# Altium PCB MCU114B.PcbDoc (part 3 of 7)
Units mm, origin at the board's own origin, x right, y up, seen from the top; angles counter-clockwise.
Board outline 105.51 x 58.76 mm, 8 copper layers (Top Layer, GND 2, Signal Layer 3, Power 4, Power 5, Signal Layer 6, GND 7, Bottom), stack 1.554 mm thick; 444 components, 418 nets, 1811 pads, 981 vias.
Unrouted connection lines stored in the file: 3.
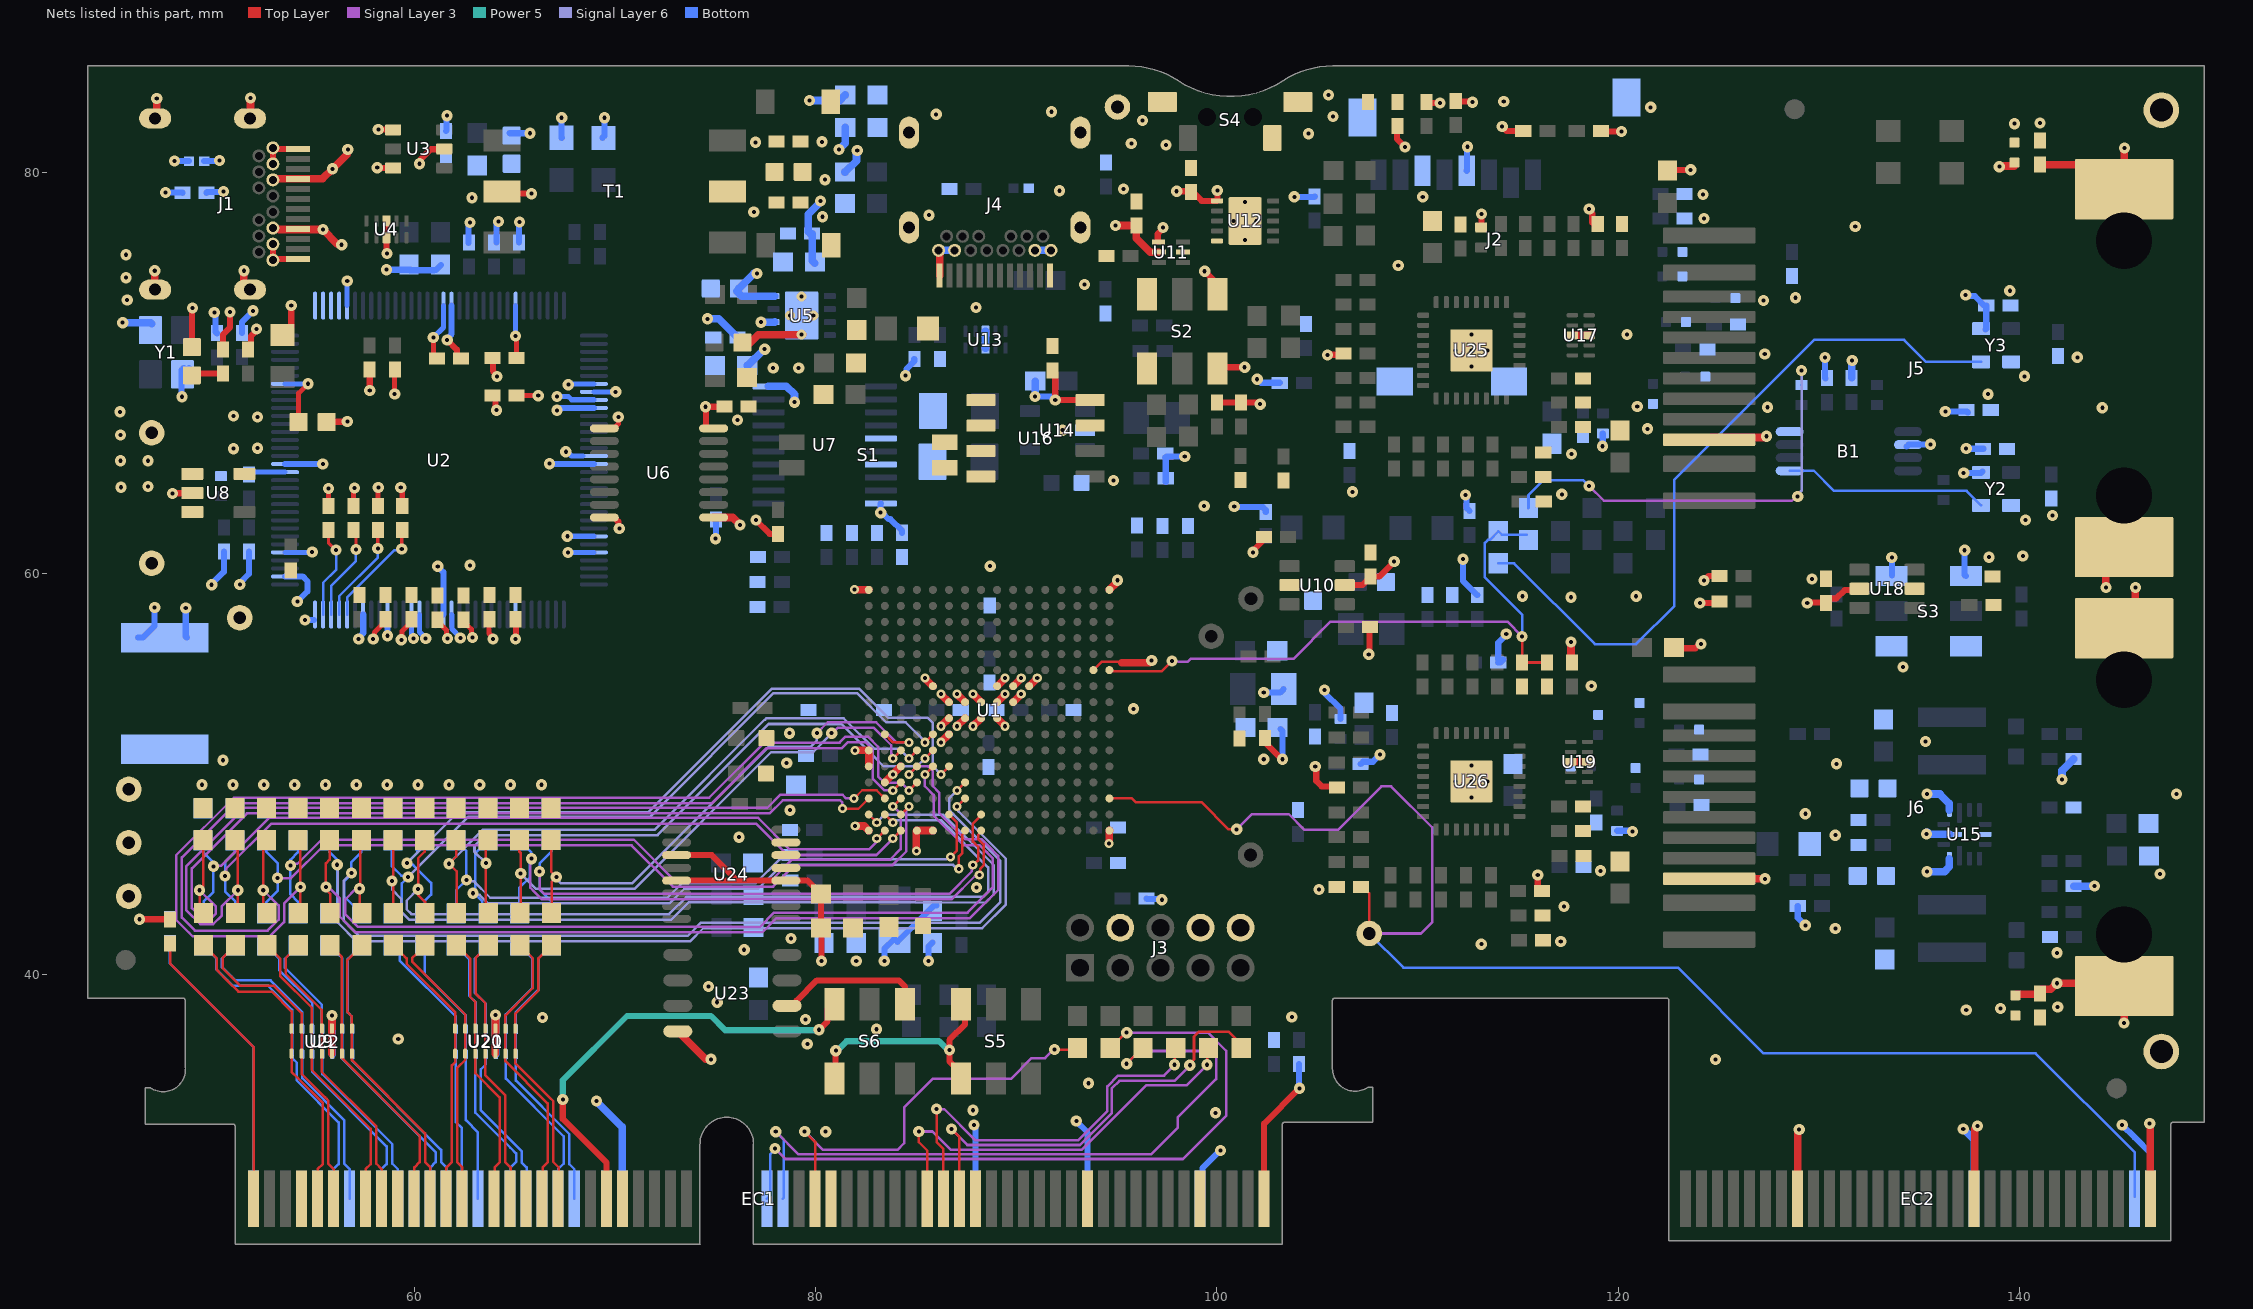
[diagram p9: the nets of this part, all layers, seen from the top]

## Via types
v1: diameter 0.559, hole 0.203, Top Layer to Bottom, tented both sides, 810 vias
v2: diameter 0.457, hole 0.203, Top Layer to Bottom, tented both sides, 153 vias
v3: diameter 0.5, hole 0.2, Top Layer to Bottom, tented both sides, 10 vias
v4: diameter 0.5, hole 0.2, Top Layer to Bottom, tented bottom, 4 vias
v5: diameter 0.5, hole 0.2, Top Layer to Bottom, tented top, 4 vias

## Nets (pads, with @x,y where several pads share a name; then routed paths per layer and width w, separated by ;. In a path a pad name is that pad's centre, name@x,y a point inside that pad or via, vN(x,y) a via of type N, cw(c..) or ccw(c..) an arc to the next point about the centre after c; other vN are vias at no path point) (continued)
3V3: B1.6 C31.1 C35.1 C36.1 C37.1 C40.2 C43.1 C64.1 C66.1 C86.2 C103.1 C152.1 C153.1 EC1.119 J2.4 J3.10 L3.1 L4.1 R1.2 R2.2 R34.1 R35.1 R36.2 R37.2 R39.2 R40.2 R42.2 R46.1 R51.2 R54.2 R61.2 R71.1 R73.1 R88.2 R89.2 R90.2 R100.2 R105.2 R106.2 R107.2 R108.1 R111.2 R130.2 R131.1 R133.2 R134.2 R137.2 R138.1 R142.1 R145.2 R151.2 R166.1 R168.2 R202.2 R204.2 R205.1 S2.1 S2.4 S3.1 S3.4 TP5.1 U6.16 U7.20 U10.5 U11.1 U12.1 U16.8 U18.5 Y2.4 Y3.4 | length 88.3
  Top Layer w0.305: v1(46.279,42.774) 46.28,42.772 47.655,42.772 R204.2@47.655,42.77 ; v1(74.499,68.326) C31.1@75.423,68.326 ; v1@74.524,68.377 74.524,67.292 74.568,67.248 U6.16@74.907,67.248 ; v1(77.02,62.671) 77.705,61.986 R100.2@78.105,61.986 ; C86.2@91.796,70.144 91.938,70.001 v1(91.938,68.662) 93.379,68.662 U16.8@93.469,68.572 ; U11.1@97.049,76.568 97.049,76.94 97.307,77.198 v1(97.307,77.267) ; v1(97.993,79.07) 98.765,79.07 99.246,78.589 U12.1@100.008,78.589 100.021,78.602 v1(100.021,79.102) ; v1(99.39,75.082) 100.023,74.45 S2.1@100.023,73.935 ; R54.2@99.997,68.537 R51.2@101.19,68.537 102.075,68.537 v1(102.159,68.453) v1@102.192,68.486 ; S2.4@100.023,70.235 100.082,70.294 v1(101.384,70.294) ; v1(101.799,61.068) 101.799,61.145 R39.2@102.343,61.689 ; EC1.119@102.357,28.836 102.357,32.583 v1(104.115,34.341) ; R46.1@102.387,51.8 102.387,51.587 v1@103.175,50.8 ; v1(104.902,50.394) 104.951,50.345 104.951,49.666 105.222,49.395 105.975,49.395 R142.1@105.975,49.347 ; v1(105.507,70.898) 105.525,70.916 106.263,70.916 R108.1@106.281,70.898 ; U10.5@106.375,59.428 107.235,59.428 C37.1@107.666,59.859 108.093,59.859 v1(108.839,60.604) ; v1(107.569,55.982) 107.606,56.018 107.606,57.316 R40.2@107.643,57.353 ; C36.1@108.976,82.303 108.976,81.684 v1(109.385,81.275) ; R36.2@110.452,83.523 110.504,83.471 v1(111.121,83.471) ; R37.2@111.934,83.573 111.969,83.537 112.719,83.537 v1(112.745,83.511) ; R134.2@113.178,77.266 113.2,77.287 v1(113.2,77.934) ; v1(114.224,82.296) 114.452,82.067 R111.2@115.275,82.067 ; v1(115.999,44.975) 115.999,44.264 R151.2@116.126,44.137 ; v1(118.563,78.188) 118.563,78.119 118.715,77.967 118.715,77.518 R107.2@118.817,77.416 ; R89.2@119.142,82.067 119.167,82.042 v1(120.167,82.042) ; v1(124.079,58.547) 124.982,58.547 R138.1@125.051,58.615 ; v1(124.289,59.668) 124.501,59.88 R137.2@125.06,59.88 ; v1(129.435,58.539) 129.461,58.564 C103.1@130.35,58.564 ; C103.1@130.364,58.549 130.364,58.619 130.511,58.767 130.882,58.767 131.298,59.182 131.983,59.182 U18.5@132.077,59.276
  Bottom w0.305: v1(46.279,42.774) 46.286,42.781 47.787,42.781 R205.1@47.794,42.788 ; v1(75.006,61.747) 75.02,61.762 75.02,62.697 R1.2@75.034,62.711 ; U7.20@83.242,63.496 83.238,63.496 83.236,63.494 v1(83.236,63.043) 83.305,63.043 83.626,62.721 83.724,62.721 84.303,62.143 C35.1@84.303,62.043 ; v1(83.418,40.684) 83.418,41.3 83.9,41.783 L4.1@83.922,41.783 ; L4.1@84.07,41.637 85.886,43.453 C66.1@86.018,43.453 ; v1(84.48,69.875) 84.529,69.924 84.529,70.215 84.912,70.598 R71.1@84.912,70.698 ; v1(90.932,68.834) 91.766,68.834 v1(91.938,68.662) ; R202.2@96.482,43.807 96.512,43.776 97.222,43.776 v1(97.252,43.746) ; R105.2@97.45,64.567 97.45,65.761 97.425,65.786 97.481,65.842 v1(98.397,65.842) ; v1(100.865,63.348) 100.893,63.319 102.287,63.319 102.435,63.172 R34.1@102.435,63.076 ; v1(102.006,69.698) 102.025,69.698 102.203,69.52 R88.2@103.134,69.52 ; v1(102.337,54.077) 103.154,54.077 L3.1@103.324,54.246 ; C64.1@103.162,52.262 103.273,52.15 v1(103.273,50.749) ; v1(103.861,78.791) 104.861,78.791 R61.2@104.877,78.807 ; R42.2@104.089,35.544 104.102,35.531 104.102,34.354 v1(104.115,34.341) ; v1(105.359,54.204) 105.359,54.077 106.172,53.264 R168.2@106.172,52.757 ; R130.2@107.162,50.504 107.285,50.626 107.776,50.626 v1(108.128,50.978) ; v1(112.269,60.724) 112.269,59.647 R145.2@112.98,58.936 ; v1(112.395,63.932) 112.395,63.863 112.447,63.811 112.447,63.274 R35.1@112.595,63.127 ; J2.4@112.457,80.093 112.475,80.111 112.475,81.269 v1(112.492,81.287) ; R133.2@114.028,55.572 114.128,55.572 114.276,55.72 114.028,55.72 114.028,56.555 114.427,56.954 v1(114.427,56.989) ; v1(119.228,66.355) 119.238,66.365 119.238,66.984 R131.1@119.249,66.995 ; R166.1@119.96,47.183 120.689,47.183 v1(120.722,47.149) ; R2.2@128.96,43.426 128.96,42.846 v1(129.337,42.469) ; v1(130.324,70.782) 130.324,69.766 R73.1@130.35,69.74 ; S3.4@133.651,59.91 v1(133.651,60.814) ; B1.6@134.388,66.337 134.495,66.443 135.571,66.443 v1(135.581,66.453) ; v1(136.319,68.089) 137.385,68.089 C43.1@137.436,68.039 ; v1(137.233,65.016) 138.097,65.016 Y2.4@138.173,65.092 ; v1(137.283,61.17) 137.283,59.945 S3.1@137.345,59.883 ; v1(137.334,73.895) 137.382,73.847 137.784,73.847 138.259,73.373 C153.1@138.359,73.373 ; v1(137.359,66.25) 137.379,66.23 138.218,66.23 C152.1@138.224,66.235 ; Y3.4@138.325,72.179 138.359,72.212 C153.1@138.359,73.347
  Bottom w0.381: v1(90.932,68.834) 90.937,68.839 90.937,69.597 R90.2@90.942,69.602
5V0: C51.1 C53.2 C54.2 R20.1 R21.2 R28.1 R29.1 R53.2 R93.2 R99.2 R103.2 TP9.1 U11.2 U15.7 U15.11 | length 7.4
  Top Layer w0.381: v1@94.945,77.353 v1(94.945,77.368) 94.952,77.362 C51.1@95.982,77.362 95.982,76.732 96.684,76.029 U11.2@97.108,76.029
  Bottom w0.381: v1(135.403,45.143) 136.278,45.143 136.523,45.387 U15.7@136.523,45.795 ; v1(135.403,49.014) 136.05,49.014 136.523,48.542 U15.11@136.523,48.22 ; R103.2@142.713,44.425 v1(143.754,44.425)
  other v1: 147.839,49.014 77.876,70.256 79.146,70.256 95.733,81.458
20MHZ_CLK: R70.1 Y3.3 | length 36.2
  Bottom w0.132: R70.1@114.027,60.521 114.815,60.521 118.847,56.49 120.904,56.49 122.805,58.39 122.805,64.69 129.775,71.66 134.26,71.66 135.354,70.566 Y3.3@138.102,70.566
25MHZ_CLK: B1.1 Y2.3 | length 10.3
  Bottom w0.127: B1.1@128.557,65.133 129.764,65.133 130.768,64.129 137.376,64.129 Y2.3@138.102,63.404
ADC_3V0_REF: S6.6 U23.6 | length 7.4
  Top Layer w0.305: U23.6@78.569,38.456 78.915,38.456 79.051,38.592 79.051,38.716 80.057,39.722 84.138,39.722 84.439,39.42 S6.6@84.439,38.617
ADC_REF: C123.1 R57.2 U24.3 U24.5 U24.12 | length 14.2
  Top Layer w0.305: U24.5@73.064,44.698 76.094,44.698 ; U24.3@73.064,45.968 74.824,45.968 76.094,44.698 ; C123.1@80.251,42.378 80.289,42.34 v1(80.289,40.684) ; C123.1@80.264,42.378 R57.2@80.264,43.764 ; R57.2@80.317,43.973 79.592,44.698 U24.12@78.514,44.698 76.094,44.698
DEBUG_ID4: R3.1 U2.63 | length 4.7
  Top Layer w0.159: R3.1@55.698,62.18 55.698,61.541 56.059,61.181 v1(56.08,61.181)
  Bottom w0.127: U2.63@55.435,57.966 55.435,59.55 56.08,60.195 v1(56.08,61.181)
DEBUG_ID5: R4.1 U2.62 | length 4.8
  Top Layer w0.159: R4.1@56.944,62.181 57.071,62.054 v1(57.071,61.206)
  Bottom w0.127: U2.62@55.835,57.966 55.835,59.391 57.071,60.627 v1(57.071,61.206)
DEBUG_ID6: R5.1 U2.61 | length 5
  Top Layer w0.159: v1(58.163,61.257) R5.1@58.163,62.181
  Bottom w0.127: U2.61@56.235,57.966 56.235,58.877 58.163,60.804 v1(58.163,61.257)
DEBUG_ID7: R6.1 U2.60 | length 5.5
  Top Layer w0.159: v1(59.357,61.231) 59.357,62.155 R6.1@59.382,62.181
  Bottom w0.127: U2.60@56.635,57.966 56.635,58.82 58.997,61.181 59.306,61.181 v1(59.357,61.231)
EMU_0: EC1.2 R205.2 | length 14.4
  Bottom w0.127: R205.2@47.794,41.588 47.794,40.573 51.984,36.382 EC1.2@51.984,28.923
EMU_1: EC1.1 R204.1 | length 14.4
  Top Layer w0.127: R204.1@47.803,41.57 47.803,40.564 51.984,36.382 51.984,32.57 EC1.1@51.984,28.923
EMU_3V3: C2.1 C3.1 C4.1 C5.1 C6.1 C7.1 C8.1 C9.1 C18.2 C30.1 R3.2 R4.2 R5.2 R6.2 R7.1 R10.2 R13.2 R14.1 TP2.1 U2.7 U2.8 U2.9 U2.16 U2.26 U2.28 U2.39 U2.47 U2.51 U2.52 U2.69 U2.79 U2.90 U2.101 U2.113 U2.122 U6.1 U8.5 | length 41.5
  Top Layer w0.127: U6.1@69.431,67.273 U6.1@69.457,67.248
  Top Layer w0.254: C18.2@54.215,67.564 54.215,68.997 v1(54.689,69.471) ; R3.2@55.698,63.38 v1(55.699,64.254) ; R4.2@56.944,63.381 56.944,64.229 v1(56.994,64.279) ; v1(57.933,56.75) 57.991,56.809 57.991,57.072 58.549,57.63 C7.1@58.549,57.73 ; R5.2@58.163,63.381 58.163,64.279 v1(58.188,64.305) ; v1(59.004,68.961) 59.004,70.156 R7.1@59.03,70.182 ; v1(59.306,64.305) 59.382,64.229 R6.2@59.382,63.381 ; v1(59.334,56.703) 59.363,56.733 59.363,57.133 59.666,57.436 59.677,57.436 59.87,57.63 C6.1@59.87,57.73 ; v1(60.931,71.772) 60.931,70.918 C9.1@61.119,70.731 ; C5.1@61.166,57.704 61.166,57.604 61.583,57.187 61.583,56.834 v1(61.642,56.776) ; C4.1@62.461,57.704 62.461,57.604 62.828,57.237 62.828,56.885 v1(62.886,56.827) ; C3.1@63.706,57.73 63.706,57.016 63.985,56.736 v1@63.985,56.72 ; v1(65.021,71.849) 65.087,71.782 C8.1@65.087,70.756 C8.1@65.106,70.776 ; C30.1@65.046,68.877 v1(66.164,68.877) ; U6.1@69.431,67.273 69.968,67.273 70.155,67.46 v1(70.155,67.818)
  Top Layer w0.305: R14.1@51.686,71.179 51.833,71.326 51.833,71.851 52.118,72.135 v1(52.118,72.204) ; C2.1@65.026,57.73 65.052,57.704 v1@65.052,56.755
  Bottom w0.254: R10.2@51.737,64.956 51.847,65.066 U2.79@53.535,65.066 ; U2.69@53.535,61.066 54.869,61.066 v1(54.892,61.089) ; U2.90@53.535,69.466 53.538,69.468 54.686,69.468 v1(54.689,69.471) ; U2.101@56.635,73.366 56.635,74.589 v1(56.639,74.592) ; U2.52@59.835,57.966 59.835,56.88 v1(59.94,56.776) ; U2.51@60.235,57.966 60.235,57.09 v1(60.549,56.776) ; v1@60.906,71.747 v1(60.931,71.772) 61.435,72.277 U2.113@61.435,73.366 ; U2.47@61.835,57.966 61.862,57.939 61.862,57.238 62.277,56.824 v1(62.277,56.801) ; v1(65.021,71.849) 65.035,71.863 U2.122@65.035,73.366 ; v1@65.026,56.72 65.035,56.729 U2.39@65.035,57.966 ; v1(67.103,68.842) 67.658,68.842 67.828,68.672 68.935,68.672 U2.9@68.935,68.666 ; v1(67.535,66.083) 67.604,66.083 67.817,65.87 U2.16@68.388,65.87 ; v1(67.612,61.866) U2.26@68.935,61.866 ; v1(67.64,61.062) 67.642,61.064 68.934,61.064 U2.28@68.935,61.066 ; v1(67.661,69.425) 67.702,69.466 U2.7@68.935,69.466 ; U2.8@68.935,69.066 68.937,69.067 70.022,69.067 v1(70.024,69.069)
  other v1: 63.909,56.745 65.026,56.745 50.975,66.235 52.168,66.261 52.168,67.81 50.975,67.861
EMU_5V0: C16.1 C17.2 C20.1 C21.1 C22.1 J1.A4 J1.A9 J1.B4 J1.B9 R15.2 R18.2 T1.5 TP1.1 U3.2 U8.1 U8.3 | length 14.7
  Top Layer w0.305: TP1.1@46.885,67.023 TP1.1@46.96,67.097 ; C17.2@49.017,70.082 49.017,69.979 C16.1@50.441,69.979 ; v1(55.905,80.188) v1@55.931,80.213 ; v1@60.169,80.522 60.249,80.522 60.283,80.557 60.283,80.637 60.81,81.163 61.458,81.163 U3.2@61.475,81.18 ; T1.5@64.354,79.062 64.466,78.95 v1(65.833,78.95)
  Top Layer w0.381: J1.B4@52.932,77.235 52.998,77.169 53.242,77.169 53.246,77.165 v1(55.423,77.165) 56.151,76.437 56.329,76.437 v1(56.363,76.403) ; J1.B9@52.932,79.635 52.982,79.685 J1.A4@54.192,79.685 55.403,79.685 v1(55.905,80.188) ; v1@55.931,80.213 56.633,80.916 56.633,81.119 v1(56.667,81.153)
  Bottom w0.305: C20.1@49.507,80.57 49.522,80.586 50.247,80.586 v1(50.262,80.601) ; R15.2@49.624,78.996 49.652,79.024 50.438,79.024 v1(50.466,79.052)
  other v1: 45.364,64.313 46.707,64.347 45.336,65.634 46.707,65.634 45.336,66.921 45.314,68.072 45.665,73.641 45.614,74.759 45.614,75.902 62.861,78.747 60.235,80.439
EMU_GND: C1.2 C2.2 C3.2 C4.2 C5.2 C6.2 C7.2 C8.2 C9.2 C10.2 C11.2 C12.2 C13.2 C14.2 C15.2 C16.2 C17.1 C18.1 C19.2 C20.2 C21.2 C22.2 C30.2 C34.2 D1.1 D5.2 D6.2 J1.A1 J1.A12 J1.B1 J1.B12 J1.M1 J1.M2 J1.S1 J1.S2 J1.S3 J1.S4 R11.1 R12.1 R15.1 R16.1 R17.2 TP3.1 U2.10 U2.17 U2.48 U2.55 U2.58 U2.64 U2.66 U2.80 U2.114 U3.4 U3.6 U4.3@58.594,76.754 U4.8@58.594,77.589 U6.8 U8.2 Y1.2 Y1.4 | length 65
  Top Layer w0.305: v1(47.927,64) 47.939,64.013 48.904,64.013 U8.2@48.943,64.051 ; C17.1@48.89,71.394 48.89,73.118 v1@48.924,73.152 ; C16.2@50.441,71.179 50.441,71.925 50.8,72.284 v1(50.8,73.05) ; J1.M1@52.932,76.435 J1.B1@52.932,75.635 52.982,75.685 J1.A12@54.192,75.685 ; J1.M2@52.932,80.435 J1.B12@52.932,81.235 52.982,81.185 J1.A1@54.192,81.185 ; D1.1@53.413,71.908 53.45,71.908 53.848,72.306 v1(53.848,73.381) ; C18.1@55.615,67.564 55.628,67.577 56.629,67.577 v1(56.642,67.589) ; v1@57.756,69.142 v1(57.76,69.139) 57.76,70.179 C1.2@57.756,70.182 ; v1(58.136,80.245) 58.144,80.238 58.918,80.238 U3.6@58.925,80.23 ; v1(58.187,82.15) 58.197,82.14 58.915,82.14 U3.4@58.925,82.13 ; U4.8@58.594,77.589 U4.3@58.594,76.754 58.594,76.005 v1(58.626,75.973) ; v1(61.62,71.653) 62.107,71.167 62.107,70.879 62.255,70.731 C9.2@62.319,70.731 ; C30.2@63.887,68.928 64.031,68.784 64.031,68.204 v1(64.08,68.155) ; C8.2@63.887,70.756 63.903,70.741 63.903,70.102 64.105,69.9 v1(64.105,69.831) ; U6.8@69.457,62.803 69.956,62.803 70.157,62.602 70.157,62.304 v1(70.206,62.255)
  Top Layer w0.381: v1(47.041,75.108) 47.041,74.186 J1.S3@47.062,74.165 ; J1.S2@47.062,82.705 47.142,82.786 v1(47.142,83.693) ; v1(51.486,75.108) 51.486,74.471 J1.S4@51.792,74.165 ; J1.S1@51.792,82.705 51.816,82.729 v1(51.816,83.718)
  Bottom w0.305: C34.2@46.199,56.812 46.453,56.812 47.038,57.396 v1(47.038,58.31) ; v1(47.57,79.001) 47.572,78.998 48.422,78.998 R15.1@48.424,78.996 ; v1(48.027,80.576) 48.03,80.573 48.747,80.573 C20.2@48.75,80.57 ; v1@48.378,69.069 48.378,70.157 Y1.4@48.484,70.263 ; v1(48.587,58.285) 48.587,56.863 C34.2@48.638,56.812 ; Y1.4@48.617,70.131 Y1.4@48.752,70.266 ; v1(49.881,59.45) 49.881,59.489 50.491,60.098 C15.2@50.491,61.111 ; v1(50.013,73.025) 50.061,72.976 50.061,72.067 C14.2@50.136,71.991 ; v1(51.284,59.467) 51.284,59.536 51.741,59.993 R11.1@51.741,61.112 ; C13.2@51.384,71.999 51.384,72.547 v1(51.946,73.109) ; U2.66@53.535,59.866 54.412,59.866 54.657,59.621 54.657,59.122 v1(54.15,58.615) ; U2.80@53.535,65.466 55.412,65.466 v1(55.42,65.473) ; v1(54.53,57.69) U2.64@54.983,57.69 ; v1(57.209,56.745) 57.209,56.817 57.435,57.043 U2.58@57.435,57.966 ; v1(58.598,75.159) R16.1@59.794,75.159 ; U2.55@58.635,57.966 58.64,57.961 v1(58.64,56.907) ; R16.1@59.769,75.133 R17.2@60.973,75.133 ; R16.1@59.769,75.135 61.051,75.135 R17.2@61.318,75.402 ; v1(61.151,60.368) 61.435,60.084 U2.48@61.435,57.966 ; C22.2@61.56,82.072 61.588,82.1 61.588,82.808 v1(61.616,82.836) ; v1(61.62,71.653) 61.62,71.722 61.842,71.944 61.842,73.359 U2.114@61.835,73.366 ; C11.2@62.69,76.497 62.69,77.442 v1(62.76,77.513) ; C12.2@64.085,76.521 64.085,77.466 v1(64.181,77.562) ; C21.2@64.738,81.977 64.756,81.96 v1(65.748,81.96) ; C10.2@65.202,76.521 65.202,77.517 v1(65.222,77.537) ; v1(66.722,65.488) 66.733,65.477 68.924,65.477 U2.17@68.935,65.466 ; v1(67.09,68.148) 67.125,68.148 67.242,68.266 U2.10@68.935,68.266 ; D5.2@67.332,81.738 67.331,81.739 v1(67.331,82.735) ; D6.2@69.364,81.738 69.465,81.838 v1(69.465,82.735)
  Bottom w0.381: v1(45.441,72.517) 46.831,72.517 Y1.2@46.884,72.463
  other v1: 62.76,60.419 48.394,68.825 48.924,73.253
ERRORSTS: EC2.178 R38.2 TP11.1 U1.P16 | length 74.7
  Top Layer w0.127: U1.P16@94.641,48.795 95.763,48.795 95.944,48.614 98.521,48.614 98.526,48.61 99.225,48.61 100.577,47.257 v1(100.987,47.257) ; R38.2@107.161,44.508 107.161,44.495 107.512,44.144 107.52,44.144 107.594,44.07 TP11.1@107.594,42.062
  Signal Layer 3 w0.127: v1(100.987,47.257) 101.743,48.013 103.582,48.013 104.351,47.244 106.052,47.244 108.205,49.397 108.689,49.397 110.726,47.36 110.726,42.614 110.174,42.062 TP11.1@107.594,42.062
  Bottom w0.127: TP11.1@107.594,42.062 109.296,40.361 122.987,40.361 127.26,36.088 140.823,36.088 145.774,31.137 EC2.178@145.774,28.93
ETH1_EARTH: C101.2 C117.2 J5.10 J5.13 J5.14 J6.10 J6.13 J6.14 pad.6 R136.2 R170.2 | length 23.8
  Top Layer w0.381: J6.10@124.544,44.792 127.321,44.792 v1(127.326,44.787) ; J5.10@124.544,66.678 124.658,66.793 127.298,66.793 127.358,66.853 v1(127.406,66.853) ; v1(139.01,80.296) 139.044,80.33 139.75,80.33 C101.2@139.813,80.393 ; C117.2@139.813,38.981 139.863,39.031 140.982,39.031 R170.2@141.032,39.081 141.032,39.181 141.141,39.291 141.568,39.291 v1@141.858,39.58 ; R136.2@141.032,80.393 J5.13@144.01,80.393 ; v1(141.88,39.58) v1@141.858,39.58 ; v1(144.323,59.309) 144.323,60.417 J5.14@145.234,61.328 ; v1(145.233,37.599) 145.233,39.321 144.974,39.58 v1@141.858,39.58 ; J6.13@145.234,57.282 145.796,57.844 v1(145.796,59.309) ; J5.13@145.234,79.168 145.248,79.183 v1(145.248,81.221)
F28P65x_25MHZ_CLK: R65.2 R75.2 | length 22
  Signal Layer 3 w0.127: v1(118.563,64.37) 119.295,63.638 128.666,63.638 128.883,63.856 v1(128.956,63.856)
  Signal Layer 6 w0.127: v1(128.956,63.856) 128.956,63.947 129.155,64.146 v1(129.155,70.136)
  Bottom w0.132: R75.2@115.53,63.276 115.534,63.279 115.534,63.921 116.281,64.668 118.265,64.668 v1(118.563,64.37) ; R65.2@129.145,69.406 129.155,69.416 v1(129.155,70.136)
F28P65x_CLK: C126.2 R41.2 R70.2 R75.1 U1.F16 | length 32.4
  Top Layer w0.127: U1.F16@94.641,55.195 94.694,55.143 97.256,55.143 v1(97.765,55.651) ; v1(115.214,56.871) C126.2@115.214,55.566 115.221,55.572 R41.2@116.459,55.572
  Signal Layer 3 w0.127: v1(97.765,55.651) 97.796,55.62 98.554,55.62 98.691,55.757 103.816,55.757 105.666,57.607 114.478,57.607 v1(115.214,56.871)
  Bottom w0.127: v1(115.214,56.871) 115.214,57.963 113.361,59.816 113.361,61.536 113.51,61.685 113.615,61.685 114.027,62.096 R70.2@114.027,62.121 114.203,61.945 R75.1@115.459,61.945
GND: B1.4 C23.2 C24.1 C25.2 C26.1 C27.2 C28.1 C29.2 C31.2 C32.2 C33.2 C34.1 C35.2 C36.2 C37.2 C38.2 C39.2 C40.1 C41.1 C42.1 C43.2 C44.2 C45.1 C46.2 C47.2 C49.2 C51.2 C52.1 C53.1 C54.1 C55.2 C56.2 C57.2 C58.2 C59.2 C60.2 C61.2 C62.2 C63.1 C64.2 C65.2 C66.2 C67.2 C68.2 C69.2 C70.2 C71.2 C72.2 C73.2 C74.2 C75.2 C76.2 C77.2 C78.2 C79.2 C80.2 C81.2 C82.2 C83.2 C84.1 C85.1 C86.1 C87.1 C88.1 C89.2 C90.2 C91.2 C92.2 C93.2 C94.2 C95.1 C96.1 C97.2 C98.2 C99.2 C100.2 C101.1 C102.1 C103.2 C104.1 C105.2 C106.2 C107.2 C108.2 C109.2 C110.2 C111.1 C112.1 C113.2 C114.1 C115.2 C116.1 C117.1 C118.1 C119.1 C120.2 C121.2 C122.2 C123.2 C124.2 C125.2 C126.1 C128.2 C129.2 C130.2 C131.2 C132.2 C133.2 C134.2 C135.2 C136.2 C137.2 C138.2 C139.2 C140.2 C141.2 C142.2 C143.2 C144.2 C145.2 C146.2 C147.2 C148.2 C149.2 C150.2 C151.2 C152.2 C153.2 D2.1 D7.1 EC1.7 EC1.10 EC1.19 EC1.22 EC1.35 EC1.38 EC1.46 EC1.47 EC1.65 EC1.83 EC1.97 EC1.111 EC2.135 EC2.157 EC2.179 J2.6 J2.S1 J2.S2 J2.S3 J2.S4 J3.4 J3.8 J4.A1 J4.A12 J4.B1 J4.B12 J4.M1 J4.M2 J4.S1 J4.S2 J4.S3 J4.S4 R22.1 R23.1 R25.1 R26.1 R27.1 R31.1 R32.2 R38.1 R41.1 R43.1 R48.1 R69.2 R72.1 R74.2 R76.2 R77.1 R95.1 R104.1 R109.1 R112.1 R113.1 R123.1 R124.1 R125.1 R127.1 R128.1 R129.1 R132.1 R135.1 R136.1 R139.2 R140.2 R141.2 R143.1 R146.1 R147.1 R159.1 R160.1 R161.1 R162.1 R163.2 R167.1 R169.1 R170.1 R171.1 R206.1 S1.3 S1.4 S2.3 S2.6 S3.3 S3.6 S4.1 S4.2 S4.3 T1.2 TP8.1 U1.A1 U1.A16 U1.F15 U1.G5 U1.G9 U1.G10 U1.G11 U1.H6 U1.H7 U1.H8 U1.H9 U1.H10 U1.J6 U1.J7 U1.J8 U1.J9 U1.K6 U1.L1 U1.M1 U1.M3 U1.N2 U1.T1 U1.T4 U1.T5 U1.T16 U5.5 U5.9@79.299,72.868 U6.9 U7.10 U7.15 U7.17 U9.5 U9.10 U10.2 U11.5 U12.5 U12.11 U13.3@88.46,71.25 U13.8@88.46,72.085 U14.2 U15.2 U15.9 U16.1 U16.2 U16.3 U16.4 U16.7 U17.3@117.725,71.887 U17.8@118.56,71.887 U18.2 U19.3@117.641,50.618 U19.8@118.476,50.618 U20.5 U20.10 U21.5 U21.10 U22.5 U22.10 U23.4 U24.13 U24.14 U24.15 U25.33 U26.33 Y2.2 Y3.2 | length 59.1
  Top Layer w0.127: U1.F15@93.841,55.195 94.247,55.601 95.254,55.601 95.291,55.638
  Top Layer w0.305: R135.1@122.463,80.094 122.506,80.137 v1(123.622,80.137) ; R169.1@122.792,56.319 122.824,56.286 123.858,56.286 124.061,56.49 v1(124.13,56.49)
  Top Layer w0.381: U9.5@55.869,36.07 U9.10@55.869,37.32 ; U9.10@55.88,37.32 v1(55.88,37.973) ; U20.5@64.022,36.07 64.022,36.906 64.033,36.917 v1(64.033,37.998) ; U23.4@73.119,37.186 74.516,35.789 v1(74.778,35.789) ; U6.9@74.907,62.803 75.856,62.803 v1(76.225,62.433) ; C26.1@76.568,71.349 77.142,71.923 v5@79.35,71.923 ; v2(81.928,59.207) 81.936,59.199 82.638,59.199 U1.A1@82.641,59.195 ; v2(81.962,51.189) 81.968,51.195 U1.L1@82.641,51.195 U1.M1@82.641,50.395 ; v2(81.966,47.422) 82.414,47.422 U1.T1@82.641,47.195 ; U1.N2@83.441,49.595 v2(83.841,49.995) U1.M3@84.241,50.395 ; v2(85.014,46.177) 85.014,47.167 U1.T4@85.041,47.195 U1.T5@85.841,47.195 ; v2(85.441,54.795) U1.G5@85.841,54.395 ; J4.B1@86.125,76.126 86.175,76.076 J4.A12@86.175,74.866 ; v2@86.212,52.39 86.236,52.39 U1.J6@86.641,52.795 ; v2(86.241,51.595) U1.K6@86.641,51.995 ; v2(86.241,53.995) U1.H6@86.641,53.595 ; v2@87.012,52.39 87.036,52.39 U1.J7@87.441,52.795 ; v2(87.041,53.995) U1.H7@87.441,53.595 ; v2@87.812,52.39 87.836,52.39 U1.J8@88.241,52.795 ; v2(87.841,53.995) U1.H8@88.241,53.595 ; U1.J9@89.041,52.795 v2(89.441,52.395) ; U1.H9@89.041,53.595 v2(89.441,53.995) ; U1.G9@89.041,54.395 v2(89.441,54.795) ; U1.H10@89.841,53.595 v2(90.241,53.995) ; U1.G10@89.841,54.395 v2(90.241,54.795) ; U1.G11@90.641,54.395 v2(91.041,54.795) ; v2(94.626,46.557) 94.626,47.18 U1.T16@94.641,47.195 ; U1.A16@94.641,59.195 94.641,59.2 95.004,59.563 95.004,59.641 v1(95.038,59.675) ; 95.254,55.567 96.639,55.567 v1(96.749,55.677) ; U19.3@117.641,50.618 U19.8@118.476,50.618 ; v1(117.653,56.591) 117.653,55.619 R143.1@117.699,55.572 ; U17.3@117.725,71.887 U17.8@118.56,71.887 ; EC2.135@128.955,28.836 128.955,32.206 v1(129.032,32.283) ; EC2.157@137.755,28.836 137.783,28.865 137.783,32.323 v1(137.922,32.461) ; v1(146.507,32.588) 146.531,32.565 146.531,28.86 EC2.179@146.555,28.836
  Bottom w0.305: v1@85.623,40.64 85.623,41.415 C66.2@85.827,41.618
  Bottom w0.381: v1(55.88,37.973) 55.88,36.684 55.896,36.668 U22.10@55.896,36.043 ; v1(64.033,37.998) 64.033,36.684 64.049,36.668 U21.10@64.049,36.043 ; U7.10@77.642,69.346 78.533,69.346 78.941,68.938 v1(78.941,68.554) ; J4.B1@86.125,76.126 J4.M1@86.925,76.126 ; U13.3@88.46,71.25 U13.8@88.46,72.085 ; J4.M2@90.925,76.126 J4.B12@91.725,76.126 ; R74.2@131.648,69.764 131.648,70.612 v1(131.674,70.637) ; v1@135.382,47.117 135.43,47.117 135.54,47.007 U15.9@136.535,47.007 ; v1(142.138,49.733) 142.138,50.189 R206.1@142.708,50.759
  other v1: 80.493,32.182 99.924,33.122 87.833,33.249 93.599,34.595 124.866,35.785 79.578,36.551 59.182,36.805 83.033,37.287 79.484,37.781 66.37,37.871 103.734,37.897 137.363,38.249 139.065,38.329 141.921,38.397 75.082,38.633 74.651,39.421 82.017,40.684 85.623,40.684 141.884,41.097 76.429,41.25 113.182,41.529 117.145,41.656 78.765,41.808 130.835,42.316 117.308,43.401 105.091,44.253 88.011,44.348 147.026,45.026 119.126,45.187 76.175,46.863 130.835,46.965 135.373,47.027 129.337,48.031 78.715,48.209 49.403,49.479 50.941,49.479 52.479,49.479 54.017,49.479 55.554,49.479 57.092,49.479 58.63,49.479 60.168,49.479 61.706,49.479 63.244,49.479 64.782,49.479 66.319,49.479 130.886,50.521 78.548,50.563 50.444,50.698 102.337,50.749 135.331,51.638 78.689,52.051 95.834,53.264 118.669,54.407 134.214,55.347 117.653,58.826 115.24,58.877 120.904,58.877 129.678,59.733 88.697,60.376 138.492,60.825 140.183,60.884 140.321,62.679 141.667,62.908 99.365,63.373 117.196,63.957 106.756,64.084 94.844,64.643 117.678,65.964 92.3,67.158 121.474,67.226 76.094,67.658 144.145,68.275 127.457,68.301 120.957,68.342 138.441,68.953 140.27,69.842 142.9,70.79 127.316,70.96 120.447,71.933 87.986,73.279 127.256,73.629 128.854,73.762 139.533,74.109 93.396,74.422 109.042,75.362 131.826,77.318 124.293,77.716 80.34,77.8 85.649,77.876 76.911,78.029 110.261,78.791 124.242,78.91 92.151,79.096 95.337,79.189 97.46,81.382 76.987,81.509 104.572,81.94 139.762,82.44 141.032,82.466 96.291,82.601 105.791,82.804 86.004,82.906 91.753,83.035 121.626,83.253 114.3,83.541 105.562,83.871
  other v2: 86.241,52.395 87.041,52.395 87.841,52.395
  other v3: 112.685,48.849 111.885,49.649 112.685,49.649 113.485,49.649 112.685,50.449 112.685,70.337 111.885,71.137 112.685,71.137 113.485,71.137 112.685,71.937
  other v4: 101.408,76.639 100.833,77.589 101.983,77.589 101.408,78.539
  other v5: 79.299,71.918 78.724,72.868 79.874,72.868 79.299,73.818
HSEC_5V0: C27.1 C28.2 EC1.48 EC1.84 EC1.98 EC1.112 EC2.158 EC2.180 R22.2 R24.2 R28.2 TP4.1 U5.8 | length 32.6
  Bottom w0.305: v1(87.884,32.512) 87.957,32.439 EC1.84@87.957,28.95 ; v1@92.985,32.711 93.557,32.139 EC1.98@93.557,28.836 ; EC1.112@99.157,28.836 99.28,28.958 99.28,30.355 v1(100.173,31.249) ; v1(145.136,32.512) 145.754,31.894 146.555,31.093 EC2.180@146.555,28.95
  Bottom w0.381: v1(69.063,33.706) 70.357,32.411 EC1.48@70.357,28.836 ; v1(74.604,72.708) 75.161,72.708 C27.1@76.089,71.78 ; C28.2@76.062,74.092 76.311,73.843 U5.8@77.95,73.843 ; C28.2@76.163,74.219 76.911,74.966 v1(77.065,74.966) ; R22.2@76.582,70.382 76.607,70.382 77.422,71.197 v1(77.45,71.197) ; v1(81.153,81.153) 81.471,81.471 R28.2@81.471,82.245 ; R24.2@81.446,80.033 81.471,80.033 82.033,80.595 82.033,81.068 v1(82.067,81.102) ; v1@137.207,32.316 137.755,31.768 EC2.158@137.755,28.836
  other v1: 137.212,32.316 92.989,32.715
HSEC_ADC-VREFHI: EC1.45 S6.4 | length 22.9
  Top Layer w0.305: v1(67.386,33.782) 67.386,32.817 69.557,30.646 EC1.45@69.557,28.836 ; v1(80.162,37.262) 80.591,37.691 80.591,38.269 S6.4@80.939,38.617
  Power 5 w0.305: v1(67.386,33.782) 67.386,34.747 70.587,37.948 74.778,37.948 75.489,37.236 80.137,37.236 v1(80.162,37.262)
HSEC_ADC_A0A1_N: EC1.11 R173.2 U9.2 U9.13 | length 16.2
  Top Layer w0.124: R173.2@51.057,41.477 50.421,40.841 50.421,40.348 50.871,39.898 51.323,39.446 52.996,39.446 54.369,38.073 54.369,37.599 U9.13@54.369,37.32 U9.2@54.369,36.07 54.369,35.054 55.533,33.89 55.533,33.888 55.621,33.801 55.621,33.799 55.7,33.72 55.7,30.569 55.957,30.312 EC1.11@55.957,28.836
HSEC_ADC_A0A1_P: EC1.9 R172.2 U9.1 U9.14 | length 16.2
  Top Layer w0.124: R172.2@49.48,41.477 50.144,40.813 50.144,40.233 50.221,40.157 50.221,40.153 50.674,39.7 50.677,39.7 51.208,39.169 52.881,39.169 53.869,38.182 53.869,37.599 53.869,35.161 54.173,34.857 54.173,34.855 55.423,33.605 55.423,30.578 55.157,30.312 EC1.9@55.157,28.836
HSEC_ADC_A2A3_N: EC1.17 R175.2 U9.4 U9.11 | length 14.9
  Top Layer w0.124: R175.2@54.211,41.477 53.573,40.839 53.573,40.051 55.369,38.256 U9.11@55.369,37.32 55.369,36.349 U9.4@55.369,36.07 55.369,35.469 55.369,35.157 58.09,32.436 58.09,30.579 58.357,30.312 EC1.17@58.357,28.836
HSEC_ADC_A2A3_P: EC1.15 R174.2 U9.3 U9.12 | length 14.9
  Top Layer w0.124: R174.2@52.63,41.477 53.296,40.811 53.296,39.937 54.869,38.364 54.869,35.262 57.81,32.32 57.81,30.565 57.557,30.312 EC1.15@57.557,28.836
HSEC_ADC_A4A5_N: EC1.23 R177.2 U9.7 U9.8 | length 14.5
  Top Layer w0.124: R177.2@57.366,41.452 56.646,40.732 56.646,38.149 56.862,37.932 56.862,37.606 56.869,37.599 U9.8@56.869,37.32 56.869,36.349 U9.7@56.869,36.07 56.869,35.75 60.526,32.093 60.526,30.659 60.784,30.4 EC1.23@60.784,28.923
HSEC_ADC_A4A5_P: EC1.21 R176.2 U9.6 U9.9 | length 14.3
  Top Layer w0.124: R176.2@55.789,41.477 56.369,40.897 56.369,37.599 U9.6@56.369,36.07 ; U9.6@56.369,35.859 60.249,31.979 60.249,30.665 59.984,30.4 EC1.21@59.984,28.923
HSEC_ADC_A8A9_N: EC1.36 R179.2 U21.4 U21.11 | length 14.1
  Bottom w0.124: R179.2@63.649,41.461 63.649,41.436 63.236,41.023 63.211,41.023 62.992,40.804 62.992,39.116 63.549,38.559 U21.4@63.549,37.293 U21.11@63.549,36.043 63.549,35.915 63.549,35.542 63.299,35.292 63.299,33.245 65.337,31.208 65.337,30.646 65.584,30.399 EC1.36@65.584,28.923
HSEC_ADC_A8A9_P: EC1.34 R178.2 U21.3 U21.12 | length 13.9
  Bottom w0.124: R178.2@62.072,41.461 62.072,41.436 62.715,40.793 62.715,38.958 63.049,38.624 U21.12@63.049,36.043 63.022,36.016 63.022,33.131 64.775,31.378 65.06,31.093 65.06,30.674 64.784,30.399 EC1.34@64.784,28.923
HSEC_ADC_A10A11_N: EC1.42 R181.2 U21.7 U21.8 | length 14.6
  Bottom w0.124: R181.2@66.828,41.477 66.152,40.8 66.152,39.242 65.049,38.139 U21.7@65.049,37.293 U21.8@65.049,36.043 65.049,34.722 67.71,32.062 67.71,30.559 67.957,30.312 EC1.42@67.957,28.836
HSEC_ADC_A10A11_P: EC1.40 R180.2 U21.6 U21.9 | length 14.8
  Bottom w0.124: R180.2@65.226,41.461 65.875,40.813 65.875,39.357 64.549,38.031 U21.9@64.549,36.043 64.549,34.83 67.433,31.947 67.433,30.588 67.157,30.312 EC1.40@67.157,28.836
HSEC_ADC_A14B14C14A15B15C15_N: EC1.27 R183.2 U20.2 U20.13 | length 14.2
  Top Layer w0.124: R183.2@60.52,41.477 60.52,41.452 60.107,41.039 60.082,41.039 59.877,40.834 59.877,40.666 62.522,38.021 62.522,37.599 62.522,36.349 62.522,35.762 62.131,35.371 62.131,30.653 62.384,30.4 EC1.27@62.384,28.923
HSEC_ADC_A14B14C14A15B15C15_P: EC1.25 R182.2 U20.1 U20.14 | length 14
  Top Layer w0.124: R182.2@58.943,41.477 58.943,41.452 59.356,41.039 59.381,41.039 59.6,40.82 59.6,40.551 62.031,38.121 62.031,37.608 62.022,37.599 62.022,36.349 62.022,35.653 61.855,35.486 61.855,30.671 61.584,30.4 EC1.25@61.584,28.923
HSEC_ADC_B0B1_N: EC1.14 R185.2 U22.2 U22.13 | length 16.6
  Bottom w0.124: R185.2@51.057,41.477 51.057,41.452 50.658,41.053 50.633,41.053 50.393,40.813 50.393,40.39 51.06,39.723 52.817,39.723 54.396,38.144 U22.2@54.396,37.293 54.396,34.848 56.481,32.762 56.481,30.588 56.757,30.312 EC1.14@56.757,28.836
HSEC_ADC_B0B1_P: EC1.12 R184.2 U22.1 U22.14 | length 16.4
  Bottom w0.124: R184.2@49.48,41.477 49.48,41.452 50.116,40.816 50.116,40.275 50.945,39.446 52.702,39.446 53.896,38.252 U22.14@53.896,36.043 ; U22.14@53.869,35.876 53.913,35.876 53.934,35.855 53.934,35.811 54.119,35.626 54.119,34.733 56.205,32.647 56.205,30.56 55.957,30.312 EC1.12@55.957,28.836
HSEC_ADC_B2B3_N: EC1.20 R187.2 U22.4 U22.11 | length 15.2
  Bottom w0.124: R187.2@54.186,41.461 53.522,40.797 53.522,40.364 55.369,38.517 55.369,37.599 U22.4@55.369,37.293 ; U22.4@55.396,37.293 U22.11@55.396,36.043 55.396,35.048 58.881,31.562 58.881,30.588 59.157,30.312 EC1.20@59.157,28.836
HSEC_ADC_B2B3_P: EC1.18 R186.2 U22.3 U22.12 | length 15.2
  Bottom w0.124: R186.2@52.609,41.461 53.246,40.825 53.246,40.249 54.896,38.598 U22.12@54.896,36.043 54.896,35.156 58.605,31.447 58.605,30.56 58.357,30.312 EC1.18@58.357,28.836
HSEC_ADC_B4B5_N: EC1.26 R189.2 U22.7 U22.8 | length 14.9
  Bottom w0.124: U22.8@56.869,36.043 56.869,35.962 56.896,35.934 56.89,35.928 56.89,35.708 61.323,31.275 61.323,30.66 61.584,30.399 EC1.26@61.584,28.923 ; U22.7@56.869,37.293 56.869,37.599 56.862,37.606 56.862,37.932 56.673,38.122 56.673,40.793 56.917,41.037 56.942,41.037 57.341,41.436 R189.2@57.341,41.461 ; U22.8@56.896,36.043 U22.7@56.896,37.293
HSEC_ADC_B4B5_P: EC1.24 R188.2 U22.6 U22.9 | length 14.8
  Bottom w0.124: R188.2@55.764,41.461 55.764,41.436 56.176,41.023 56.201,41.023 56.396,40.829 U22.6@56.396,37.293 U22.9@56.396,36.043 56.396,35.81 61.046,31.16 61.046,30.66 60.784,30.399 EC1.24@60.784,28.923
HSEC_ADC_C2C3_N: EC1.33 R191.2 U20.4 U20.11 | length 13.5
  Top Layer w0.124: 63.522,36.349 63.522,37.599 63.522,38.586 63.039,39.069 63.039,40.842 R191.2@63.674,41.477 ; 63.523,36.349 63.523,34.989 64.507,34.004 64.507,33.46 64.51,33.458 64.51,30.674 64.784,30.4 EC1.33@64.784,28.923
HSEC_ADC_C2C3_P: EC1.31 R190.2 U20.3 U20.12 | length 13.5
  Top Layer w0.124: R190.2@62.097,41.477 62.762,40.812 62.762,38.954 62.763,38.953 62.763,38.91 63.022,38.651 63.022,37.599 63.022,35.098 64.23,33.89 64.23,30.646 63.984,30.4 EC1.31@63.984,28.923
HSEC_ADC_C4: EC1.30 R192.2 U21.2 U21.13 | length 13.7
  Bottom w0.127: R192.2@60.495,41.461 60.495,40.038 62.549,37.984 U21.2@62.549,37.293 62.549,32.752 63.157,32.144 EC1.30@63.157,28.836
HSEC_ADC_C6: EC1.28 R193.2 U21.1 U21.14 | length 14
  Bottom w0.127: R193.2@58.918,41.461 59.254,41.125 59.254,40.72 62.049,37.925 U21.14@62.049,36.043 62.049,32.663 62.357,32.355 EC1.28@62.357,28.836
HSEC_ADC_C10C11_N: EC1.39 R195.2 U20.7 U20.8 | length 14.2
  Top Layer w0.124: R195.2@66.828,41.477 66.167,40.816 66.167,39.218 65.022,38.073 65.022,37.599 65.022,36.349 65.022,35.589 66.744,33.867 66.746,33.867 66.91,33.703 66.91,30.674 67.184,30.4 EC1.39@67.184,28.923
HSEC_ADC_C10C11_P: EC1.37 R194.2 U20.6 U20.9 | length 14.4
  Top Layer w0.124: R194.2@65.251,41.477 65.89,40.838 65.89,39.342 65.338,38.79 64.825,38.277 64.522,37.974 64.522,37.599 64.522,35.698 66.633,33.587 66.633,30.649 66.384,30.4 EC1.37@66.384,28.923
HSEC_GPIO11: EC1.63 R96.1 | length 20.7
  Top Layer w0.127: v1(79.447,32.189) 79.968,31.668 79.968,28.846 EC1.63@79.957,28.836 ; v1(91.897,36.271) 92.981,36.271 R96.1@93.051,36.342
  Signal Layer 3 w0.127: v1(79.447,32.189) 79.453,32.189 80.368,31.274 84.072,31.274 84.4,31.603 84.4,33.394 85.822,34.817 89.735,34.817 90.762,35.844 91.428,35.844 91.855,36.271 v1(91.897,36.271)
HSEC_GPIO12: EC1.58 R45.2 | length 36
  Top Layer w0.127: R45.2@94.683,36.342 95.457,37.116 v1(95.5,37.116)
  Signal Layer 3 w0.127: v1(77.969,31.337) 78.489,30.817 98.305,30.817 100.457,32.969 100.457,36.216 99.557,37.116 v1(95.5,37.116)
  Bottom w0.127: EC1.58@77.557,28.836 77.724,29.003 77.724,31.047 77.969,31.292 v1(77.969,31.337)
HSEC_GPIO13: EC1.60 R47.2 | length 35
  Top Layer w0.127: v1(95.5,35.567) 96.262,36.329 96.262,36.425 R47.2@96.316,36.479
  Signal Layer 3 w0.127: v1(78.003,32.182) 79.14,31.046 96.713,31.046 98.04,32.373 98.04,32.889 99.957,34.806 99.957,35.884 99.64,36.202 96.135,36.202 v1(95.5,35.567)
  Bottom w0.127: v1(78.003,32.182) 78.413,31.772 78.413,28.892 EC1.60@78.357,28.836
HSEC_GPIO25: EC1.77 R98.1 | length 21
  Top Layer w0.127: v1(85.137,32.189) 85.137,31.653 85.557,31.232 EC1.77@85.557,28.836 ; v1(99.513,35.516) 99.513,36.409 R98.1@99.583,36.479
  Signal Layer 3 w0.127: v1(85.137,32.189) 85.82,32.189 86.721,31.287 93.268,31.287 93.904,31.923 96.468,34.487 98.484,34.487 v1(99.513,35.516)
HSEC_GPIO26: EC1.79 R50.2 | length 20.4
  Top Layer w0.127: v1(86.026,33.306) 86.026,31.656 86.357,31.325 EC1.79@86.357,28.836 ; R50.2@97.78,36.342 R50.2@97.877,36.245 ; v1(97.887,35.516) 97.887,36.28 R50.2@97.949,36.342
  Signal Layer 3 w0.127: v1(86.026,33.306) 86.407,33.306 87.969,31.744 93.078,31.744 94.539,33.205 94.539,34.442 95.072,34.976 97.368,34.976 97.887,35.495 v1(97.887,35.516)
HSEC_GPIO27: EC1.81 R56.2 | length 22.4
  Top Layer w0.127: v1(86.762,32.316) 87.157,31.921 EC1.81@87.157,28.836 ; v1(98.649,35.491) 98.649,35.572 98.858,35.781 98.858,36.919 99.107,37.167 100.58,37.167 100.951,36.796 R56.2@100.951,36.479
  Signal Layer 3 w0.127: v1(86.762,32.316) 87.562,31.516 93.173,31.516 94.767,33.11 94.767,34.348 95.136,34.716 97.875,34.716 v1(98.649,35.491)
"Int. V_REF": S5.1 S5.4 S6.1 | length 11.7
  Top Layer w0.305: S6.1@80.939,34.917 80.988,34.966 80.988,36.208 v1(81.001,36.22) ; S5.1@87.431,34.917 86.665,35.683 86.665,36.754 87.431,37.52 S5.4@87.431,38.617
  Power 5 w0.305: v1(81.001,36.22) 81.069,36.22 81.541,36.692 86.15,36.692 86.596,36.246 v1(86.665,36.246)
ISO_Pout_5V0: C23.1 C24.2 C25.1 C29.1 D1:A.1 D2:A.1 R23.2 R29.2 U5.6 | length 6.1
  Bottom w0.381: v1(77.267,72.542) 77.269,72.545 77.947,72.545 U5.6@77.95,72.548 ; v1(79.68,83.591) 81.191,83.591 R29.2@81.471,83.871 ; R23.2@79.956,75.481 79.819,75.617 C29.1@79.819,76.954 79.738,76.954 79.629,77.064 79.629,77.93 80.239,78.539 v1(80.239,78.588)
  other v1: 80.464,79.646 80.315,81.534
ITCK: U2.100
ITDI: U2.98
ITDO: U2.97
ITMS: U2.99
MCU_A0A1_N: C128.1 R173.1 U1.P2 | length 46.5
  Top Layer w0.124: C128.1@51.033,46.72 51.183,46.57 v1(51.183,44.218) 51.183,43.202 R173.1@51.057,43.077 ; v2(81.911,48.8) 82.315,49.204 83.032,49.204 U1.P2@83.441,48.795
  Signal Layer 3 w0.124: v1(51.183,44.218) 50.37,43.405 50.37,42.938 49.954,42.522 49.314,42.522 48.618,43.218 48.618,45.422 51.523,48.327 77.339,48.327 77.344,48.322 77.58,48.322 78.241,48.983 78.473,48.983 78.474,48.982 81.105,48.982 81.106,48.98 81.334,48.98 81.514,48.8 v2(81.911,48.8)
MCU_A0A1_P: C140.1 R172.1 U1.P1 | length 44.5
  Top Layer w0.124: C140.1@49.455,46.72 49.455,44.396 v1(49.278,44.218) 49.278,43.28 R172.1@49.48,43.077 ; v2(81.327,48.292) 81.339,48.28 82.126,48.28 U1.P1@82.641,48.795
  Signal Layer 3 w0.124: v1(49.278,44.218) 50.09,43.405 50.09,43.05 49.839,42.799 49.428,42.799 48.895,43.332 48.895,45.307 51.637,48.05 77.225,48.05 77.23,48.045 77.694,48.045 78.352,48.702 80.989,48.702 80.99,48.701 81.218,48.701 81.308,48.612 81.308,48.311 v2(81.327,48.292)
MCU_A2A3_N: C129.1 R175.1 U1.N4 | length 56.6
  Top Layer w0.124: C129.1@54.187,46.72 54.305,46.602 v1(54.305,44.374) 54.305,43.171 R175.1@54.211,43.077
  Top Layer w0.127: v2(84.641,49.195) U1.N4@85.041,49.595
  Signal Layer 3 w0.124: v1(54.305,44.374) 53.49,43.558 53.49,42.634 52.785,41.929 52.217,41.929 52.214,41.926 48.926,41.926 48.762,42.09 48.762,42.094 48.115,42.741 48.115,45.967 50.978,48.829 74.681,48.829 77.434,51.582 81.188,51.582 81.482,51.877 82.602,51.877 83.106,51.372 83.106,49.899 83.416,49.589 84.248,49.589 v2(84.641,49.195)
MCU_A2A3_P: C141.1 R174.1 U1.N3 | length 54.1
  Top Layer w0.124: C141.1@52.61,46.72 52.453,46.563 v1(52.453,44.218) 52.453,43.254 R174.1@52.63,43.077
  Top Layer w0.127: v2(83.841,49.195) U1.N3@84.241,49.595
  Signal Layer 3 w0.124: v1(52.453,44.218) 53.213,43.458 53.213,42.748 52.671,42.206 49.042,42.206 49.042,42.208 49.04,42.208 48.392,42.856 48.392,45.852 51.093,48.553 74.796,48.553 77.549,51.306 81.303,51.306 81.597,51.6 82.487,51.6 82.829,51.257 82.829,49.784 83.419,49.195 v2(83.841,49.195)
MCU_A4A5_N: C130.1 R177.1 U1.M5 | length 46.9
  Top Layer w0.124: C130.1@57.341,46.72 57.252,46.631 57.291,46.631 57.291,44.337 v1(57.252,44.298) 57.252,43.191 R177.1@57.366,43.077
  Top Layer w0.127: v2(85.441,49.995) U1.M5@85.841,50.395
  Signal Layer 3 w0.124: v1(57.252,44.298) 57.077,44.298 56.551,43.771 56.551,43.007 57.165,42.393 77.216,42.393 77.926,43.103 87.568,43.103 88.819,44.354 88.819,45.823 88.542,46.099 88.542,46.103 88.172,46.473 87.354,46.473 85.876,47.951 85.876,48.973 85.445,49.403 v2@85.445,49.995
MCU_A4A5_P: C142.1 R176.1 U1.M4 | length 49.4
  Top Layer w0.124: C142.1@55.764,46.72 55.764,45.745 55.575,45.556 v1(55.575,44.374) 55.575,44.257 55.789,44.044 R176.1@55.789,43.077
  Top Layer w0.127: v2(84.641,49.995) U1.M4@85.041,50.395
  Signal Layer 3 w0.124: v1(55.575,44.374) 55.698,44.374 56.272,43.801 56.272,42.895 57.05,42.116 77.331,42.116 78.041,42.826 87.682,42.826 89.096,44.239 89.096,45.937 88.819,46.214 88.819,46.218 88.287,46.75 87.469,46.75 86.153,48.066 86.153,49.088 85.834,49.406 85.834,50.157 85.718,50.273 85.718,50.275 85.604,50.389 85.035,50.389 v2(84.641,49.995)
MCU_A8A9_N: C131.1 R179.1 U1.T7 | length 31.6
  Top Layer w0.124: v2(87.13,45.286) 87.138,45.294 87.138,45.91 87.309,46.08 87.309,46.988 87.441,47.12 U1.T7@87.441,47.195
  Signal Layer 6 w0.124: v1(62.916,44.069) 62.999,43.986 63.236,43.986 63.656,43.566 72.712,43.566 73.441,44.295 77.122,44.295 78.309,45.482 86.845,45.482 87.04,45.286 v2(87.13,45.286)
  Bottom w0.124: v1(62.916,44.069) v1@62.973,44.126 ; R179.1@63.649,43.061 63.367,43.344 63.367,43.675 62.973,44.069 v1@62.973,44.126 ; C131.1@63.649,46.695 63.028,46.074 63.028,44.182 v1@62.973,44.126
MCU_A8A9_P: C143.1 R178.1 U1.R6 | length 31.8
  Top Layer w0.124: U1.R6@86.641,47.995 87.032,47.604 87.032,46.195 v2(86.711,45.874)
  Signal Layer 6 w0.124: v1(62.584,44.733) 62.641,44.676 62.938,44.676 63.771,43.842 72.597,43.842 73.245,44.491 73.326,44.572 77.007,44.572 78.195,45.759 86.506,45.759 86.621,45.874 v2(86.711,45.874)
  Bottom w0.124: R178.1@62.072,43.061 62.072,44.221 v1(62.584,44.733) 62.584,46.184 C143.1@62.073,46.695
MCU_A10A11_N: C132.1 R181.1 U1.R8 | length 30.4
  Top Layer w0.124: v2(87.829,45.473) 87.866,45.473 88.09,45.696 88.09,46.385 87.832,46.643 87.832,47.542 88.241,47.952 U1.R8@88.241,47.995
  Signal Layer 3 w0.124: v1(66.226,45.158) 66.226,44.276 66.46,44.041 86.657,44.041 87.778,45.162 87.778,45.422 v2(87.829,45.473)
  Bottom w0.124: C132.1@66.803,46.72 66.804,46.131 66.226,45.553 v1(66.226,45.158) 66.226,44.256 66.828,43.653 R181.1@66.828,43.077
MCU_A10A11_P: C144.1 R180.1 U1.T8 | length 31.2
  Top Layer w0.124: v2(88.152,44.981) 88.191,45.02 88.191,45.28 88.367,45.456 88.367,46.499 88.109,46.757 88.109,46.988 88.241,47.12 U1.T8@88.241,47.195
  Signal Layer 3 w0.124: v1(65.819,45.793) 65.768,45.742 65.768,44.341 65.949,44.161 66.345,43.764 86.772,43.764 87.925,44.917 88.089,44.917 v2(88.152,44.981)
  Bottom w0.124: R180.1@65.226,43.061 65.226,44.35 65.743,44.867 65.743,45.717 v1(65.819,45.793) 65.819,46.102 C144.1@65.226,46.695
MCU_A14B14C14A15B15C15_N: C133.1 R183.1 U1.R2 | length 42.3
  Top Layer w0.124: C133.1@60.504,46.72 60.504,46.144 60.173,45.812 v1(60.173,44.272) 60.173,43.988 60.52,43.64 R183.1@60.52,43.077
  Top Layer w0.127: U1.R2@83.441,47.995 v2(83.841,47.595)
  Signal Layer 6 w0.124: v1(60.173,44.272) 59.606,43.706 59.606,43.264 59.842,43.028 72.69,43.028 73.547,43.885 85.084,43.885 85.085,43.884 88.345,43.884 88.595,44.134 88.595,45.356 86.241,47.71 84.047,47.71 83.931,47.595 v2(83.841,47.595)
MCU_A14B14C14A15B15C15_P: C145.1 R182.1 U1.R1 | length 44.7
  Top Layer w0.124: C145.1@58.93,46.72 58.93,44.731 v1(58.877,44.679) 58.943,44.613 R182.1@58.943,43.077
  Top Layer w0.127: U1.R1@82.641,47.995 v2(83.041,47.595)
  Signal Layer 6 w0.124: v1(58.877,44.679) 58.877,44.247 59.329,43.795 59.329,43.149 59.728,42.751 72.804,42.751 73.662,43.608 84.969,43.608 84.971,43.607 88.46,43.607 88.872,44.019 88.872,45.471 86.356,47.987 83.434,47.987 v2(83.041,47.595)
MCU_B0B1_N: C134.1 R185.1 U1.T3 | length 40.1
  Top Layer w0.127: v2(83.841,46.795) U1.T3@84.241,47.195
  Signal Layer 3 w0.127: v1(50.548,44.929) 50.598,44.98 50.598,45.289 52.852,47.543 77.015,47.543 78.582,45.976 83.022,45.976 v2(83.841,46.795)
  Bottom w0.124: C134.1@51.033,46.695 51.033,46.119 50.548,45.633 v1(50.548,44.929) 50.548,44.163 51.057,43.653 R185.1@51.057,43.077
MCU_B0B1_P: C146.1 R184.1 U1.T2 | length 39.7
  Top Layer w0.127: v2(83.041,46.795) U1.T2@83.441,47.195
  Signal Layer 3 w0.127: v1(49.963,45.412) 50.046,45.495 50.091,45.45 50.363,45.45 52.736,47.822 77.131,47.822 78.698,46.255 82.648,46.255 83.041,46.649 v2(83.041,46.795)
  Bottom w0.124: C146.1@49.455,46.695 49.456,46.119 49.963,45.611 v1(49.963,45.412) 49.963,44.136 49.48,43.653 R184.1@49.48,43.077
MCU_B2B3_N: C135.1 R187.1 U1.P3 | length 39.3
  Top Layer w0.127: v2(83.841,48.395) U1.P3@84.241,48.795
  Signal Layer 3 w0.124: v1(53.803,45.458) 53.874,45.529 54.146,45.529 55.353,46.736 70.93,46.736 72.987,44.679 77.753,44.679 78.822,45.748 83.711,45.748 84.234,46.271 84.234,48.036 83.875,48.395 v2(83.841,48.395)
  Bottom w0.124: R187.1@54.186,43.061 54.186,43.637 53.803,44.021 v1(53.803,45.458) 53.803,45.734 54.187,46.119 C135.1@54.187,46.695
MCU_B2B3_P: C147.1 R186.1 U1.R3 | length 40.6
  Top Layer w0.127: U1.R3@84.241,47.995 v2(84.641,48.395)
  Signal Layer 3 w0.124: v1(53.168,44.823) 53.832,44.823 55.468,46.459 70.815,46.459 72.873,44.402 77.867,44.402 78.937,45.471 83.825,45.471 84.511,46.157 84.511,48.174 84.641,48.305 v2(84.641,48.395)
  Bottom w0.124: R186.1@52.609,43.061 52.609,43.625 53.168,44.183 v1(53.168,44.823) 53.168,45.573 52.61,46.131 C147.1@52.61,46.695
MCU_B4B5_N: C136.1 R189.1 U1.N7 | length 48
  Top Layer w0.127: v2(87.041,49.195) U1.N7@87.441,49.595
  Signal Layer 6 w0.124: v1(56.847,45.082) 56.844,45.082 56.454,44.693 56.454,42.712 57.224,41.942 73.616,41.942 74.274,42.6 88.183,42.6 89.207,43.624 89.207,45.672 86.851,48.028 86.851,48.03 86.701,48.18 86.699,48.18 86.648,48.232 86.648,48.801 v2(87.041,49.195)
  Bottom w0.124: R189.1@57.341,43.061 56.49,43.912 56.49,44.662 56.847,45.02 56.847,45.624 57.341,46.119 C136.1@57.341,46.695
MCU_B4B5_P: C148.1 R188.1 U1.P7 | length 47.8
  Top Layer w0.127: v2(87.041,48.395) U1.P7@87.441,48.795
  Signal Layer 6 w0.124: v1(56.136,45.488) 56.178,45.446 56.178,42.597 57.109,41.665 73.731,41.665 74.389,42.323 88.297,42.323 89.484,43.51 89.484,45.787 87.128,48.143 87.128,48.145 87.105,48.168 87.105,48.331 v2(87.041,48.395)
  Bottom w0.124: R188.1@55.764,43.061 56.136,43.433 v1(56.136,45.488) 56.136,45.747 55.764,46.119 C148.1@55.764,46.695
MCU_C2C3_N: C137.1 R191.1 U1.L5 | length 31.4
  Top Layer w0.124: C137.1@63.649,46.72 63.551,46.622 v1(63.551,45.568) 63.536,45.552 63.536,43.216 R191.1@63.674,43.077
  Top Layer w0.127: v2(85.441,50.795) U1.L5@85.841,51.195
  Signal Layer 6 w0.127: v1(63.551,45.568) 62.983,46.136 62.983,46.414 63.533,46.965 71.973,46.965 72.107,46.965 77.649,52.507 81.279,52.507 82.699,51.086 83.384,50.401 85.048,50.401 v2(85.441,50.795)
MCU_C2C3_P: C149.1 R190.1 U1.L4 | length 31.3
  Top Layer w0.124: C149.1@62.072,46.72 62.072,45.899 v1(61.713,45.539) 62.097,45.155 R190.1@62.097,43.077
  Top Layer w0.127: v2(84.641,50.795) U1.L4@85.041,51.195
  Signal Layer 6 w0.127: v1(61.713,45.539) 63.417,47.244 71.973,47.244 77.455,52.726 77.473,52.726 77.533,52.786 81.394,52.786 82.897,51.283 84.153,51.283 v2(84.641,50.795)
MCU_C4: C150.1 R192.1 U1.M6 | length 38.6
  Top Layer w0.127: v2(86.241,49.995) U1.M6@86.641,50.395
  Signal Layer 6 w0.127: v1(59.614,45.568) 62.148,48.102 71.635,48.102 77.807,54.274 82.153,54.274 83.603,52.823 85.57,52.823 85.835,52.558 85.835,50.401 v2(86.241,49.995)
  Bottom w0.127: R192.1@60.495,43.061 60.495,43.68 60.82,44.006 60.82,44.588 59.923,45.485 59.696,45.485 v1(59.614,45.568) 60.125,46.079 60.125,46.324 C150.1@60.496,46.695
MCU_C6: C138.1 R193.1 U1.K5 | length 35.6
  Top Layer w0.127: v2(85.441,51.595) U1.K5@85.841,51.995
  Signal Layer 6 w0.127: v1(59.676,44.882) 62.667,47.873 71.729,47.873 77.902,54.045 82.058,54.045 83.508,52.595 84.483,52.595 85.441,51.636 v2(85.441,51.595)
  Bottom w0.127: R193.1@58.918,43.061 58.918,43.086 59.329,43.498 59.329,43.545 59.356,43.572 59.356,44.562 v1(59.676,44.882) 59.611,44.947 59.331,44.947 58.852,45.426 58.852,46.628 C138.1@58.918,46.695
MCU_C10C11_N: C139.1 R195.1 U1.K2 | length 26.9
  Top Layer w0.124: C139.1@66.804,46.72 66.804,45.139 v1(67.064,44.879) 66.828,44.643 R195.1@66.828,43.077 ; U1.K2@83.441,51.995 83.847,51.589 v2(84.648,51.589)
  Signal Layer 3 w0.124: v1(80.056,52.051) 80.598,52.593 83.013,52.593 84.016,51.589 v2(84.648,51.589)
  Signal Layer 6 w0.124: v1(67.064,44.879) 67.064,44.798 67.302,44.56 70.843,44.56 77.659,51.376 79.751,51.376 80.036,51.661 80.036,52.031 v1(80.056,52.051)
MCU_C10C11_P: C151.1 R194.1 U1.L3 | length 27.5
  Top Layer w0.124: C151.1@65.226,46.72 65.226,46.144 65.286,46.085 v1(65.286,45.056) 65.286,43.112 R194.1@65.251,43.077
  Top Layer w0.127: v2(83.841,50.795) U1.L3@84.241,51.195
  Signal Layer 3 w0.124: v1@80.793,52.026 81.083,52.316 82.898,52.316 83.764,51.449 83.764,51.034 83.778,51.021 83.778,50.885 83.764,50.872 v2(83.841,50.795)
  Signal Layer 6 w0.124: v1(65.286,45.056) 66.059,44.283 70.958,44.283 77.773,51.099 79.866,51.099 80.793,52.026 v1(80.793,52.051)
